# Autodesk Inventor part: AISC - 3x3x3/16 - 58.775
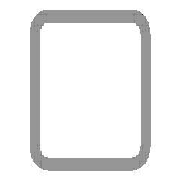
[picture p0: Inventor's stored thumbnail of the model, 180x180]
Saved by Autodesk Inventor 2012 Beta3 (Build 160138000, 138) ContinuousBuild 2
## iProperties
_CCFamilyMember: 9
_CCFamilyDisplayName: ANSI AISC (Square) - Tube
_FrameMemberDoc: Frame Member File
_Version: 15.0.0
_GetPNFromCC: 1
Created: 2011-01
Part Number: AISC - 3x3x3/16 - 58.775
Material: Steel, Mild
Description: Tube
Document SubType Name: Modeling
Standard: ANSI
Designer: Beta-8540w
Standards Organization: ANSI
Language: en-US
Size Designation: 3x3x3/16
Categories: <MemberInstance><Categories><Category DisplayName="Structural Shapes" InternalName="089c4875-fa83-4c05-b084-43b9cc11f5ed" Mnemonic="GRDR"><CategoryParameter Dis
Stock Number: 3x3x3/16
Density: 7.86 g/cm^3
IsCustomPart: 1
G_L: 58.775 in
G_W: 3.000 in
G_H: 3.000 in
+C0B2F2CA-6D80-4947-9DF6-0D09030B4A40+CUTDETAIL1: Cut
Author: Beta-8540w
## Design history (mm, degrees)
node "Start plane"
node "End plane"
sketch "Sketch"
  geometry: L1 (-38.1, -28.575)-(-38.1, 28.575); L2 (-28.575, 38.1)-(28.575, 38.1); L3 (38.1, 28.575)-(38.1, -28.575); L4 (28.575, -38.1)-(-28.575, -38.1); L5 (-28.575, 33.337)-(28.575, 33.338); L6 (33.338, 28.575)-(33.338, -28.575); L7 (28.575, -33.337)-(-28.575, -33.338); L8 (-33.338, -28.575)-(-33.338, 28.575); L9 (0, 56.102)-(0, -56.102) reference; L10 (-56.102, 0)-(56.102, 0) reference; A1 r 9.525 centre (-28.575, -28.575) between (-38.1, -28.575) and (-28.575, -38.1); A2 r 9.525 centre (-28.575, 28.575) between (-28.575, 38.1) and (-38.1, 28.575); A3 r 9.525 centre (28.575, 28.575) between (38.1, 28.575) and (28.575, 38.1); A4 r 9.525 centre (28.575, -28.575) between (28.575, -38.1) and (38.1, -28.575); A5 r 4.763 centre (-28.575, 28.575) between (-28.575, 33.337) and (-33.338, 28.575); A6 r 4.763 centre (28.575, 28.575) between (33.338, 28.575) and (28.575, 33.338); A7 r 4.763 centre (28.575, -28.575) between (28.575, -33.337) and (33.338, -28.575); A8 r 4.763 centre (-28.575, -28.575) between (-33.338, -28.575) and (-28.575, -33.338)
  constraints: 16 end point, 16 point on circle, 8 centre point, 8 tangent, 4 parallel, 3 equal radius, 2 perpendicular, 7 other
  dimensions: "d10" = 76.2 distance between parallel lines of L2 L4 (= G_H); "d11" = 76.2 distance between parallel lines of L1 L3 (= G_W); "d12" = 4.7625 distance between parallel lines of L3 L6 (= G_T); "d15" = 38.1 distance between parallel lines of L2 L10 (= 0.5 x d10); "d16" = 38.1 distance between parallel lines of L9 L3 (= 0.5 x d11); "d17" = 9.525 radius of A1 (= G_IR)
extrude "Body" new body sketch "Sketch" stored distance "d3" = 1492.89148 (= G_L); taper "d4" = 0 deg
node "Driven Length"
  sketch "Sketch3"
    geometry: L1 (0, 0)-(10, 0) reference
    constraints: 2 end point, 1 horizontal
  workplane "Work Plane3"
  sketch "Sketch4"
    geometry: L1 (-2, 31.109)-(12, 31.109) reference; L2 (-2, 1524)-(12, 1524) reference
    dimensions: "d19" = 1492.89148 distance between parallel lines of L1 L2 (derived)
workplane "Work Plane4"
split "Split1"
body "Solid1"
other parameters: "G_W" = 76.2 [user parameter; used in 1 equation term], "G_H" = 76.2 [user parameter; used in 1 equation term], "G_T" = 4.7625 [user parameter; used in 1 equation term], "G_IR" = 9.525 [user parameter; used in 1 equation term], "G_L" = 1492.89148 (= d19) [user parameter; used in 1 equation term], "G_OFFSET_START" = -31.10852 [user parameter; used in 1 equation term], "G_OFFSET_END" = 0 [user parameter; used in 1 equation term], "d13" = 31.10852 (= -G_OFFSET_START), "d14" = 1524 (= G_OFFSET_END + B_L), "B_L" = 1524 [user parameter; used in 1 equation term], "d18" = 90 deg
